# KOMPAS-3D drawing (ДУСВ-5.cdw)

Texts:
  Автопилот стабилизации угла крена
  Датчик угловых скоростей волоконный ДУСВ-5
  xdev
  Ось чувствительности
  (устанавливается по оси X ЛА)
  Технические характеристики:
  1. Диапазон измеряемых скоростей,  /с . . . . . . .  200
  2. Масса, г . . . . . . . . . . . . . . . . . . .. . . . . . . . . . . . . 130
  3. Время готовности, с . . . . . . . . . . . . . . . . не более 1
  4. Напряжение питния, В . . . . . . . . . . . . . . . . .  12 0,6
  5. Срок службы . . . . . . . . . . . . . . . . . . . . . . . . .  25 лет
  ДУСВ-5
  Светоделитель
  Microsoft Sans Serif
  Волоконный контур
  Фотодетектор
  Электронное устройство
  обработки
  Принципиальная схема ВОГ
  Источник света
  POLYLINE_STYLE_0.60_RGB_0_0_255
  ANSI37
  Датчик угловых скоростей
  волоконный
  Окоемов Б.Н.
  Пашинин С.А.
  МГТУ им. Н.Э. Баумана
  Кафедра ИУ2
  Группа ИУ2-102
Dimensions and other numbers on the sheet: 7; 4; 20max; 10; 330; 31; 29,5; 2; 3; 6; 5; 1; 4отв.; 60,8; 82; 19; 25; 24; 1,5; 0,8max; 1,5max; 2,5:1; 0; 8; 9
